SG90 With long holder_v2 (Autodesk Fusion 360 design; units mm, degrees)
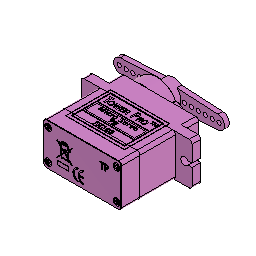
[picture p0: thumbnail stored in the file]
part number: SG90 - Micro Servo 9g - Tower Pro.1
base_feature "Base Feature"
component_insert "Component Insert1"
component_insert "Component Insert2"
joint "Assemble" alignAngle 0 alignOffsetX 0 alignOffsetY 0 alignOffsetZ 0
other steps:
joint_origin "JointOrigin2"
